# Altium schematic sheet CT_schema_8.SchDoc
size 308 x 210 mm
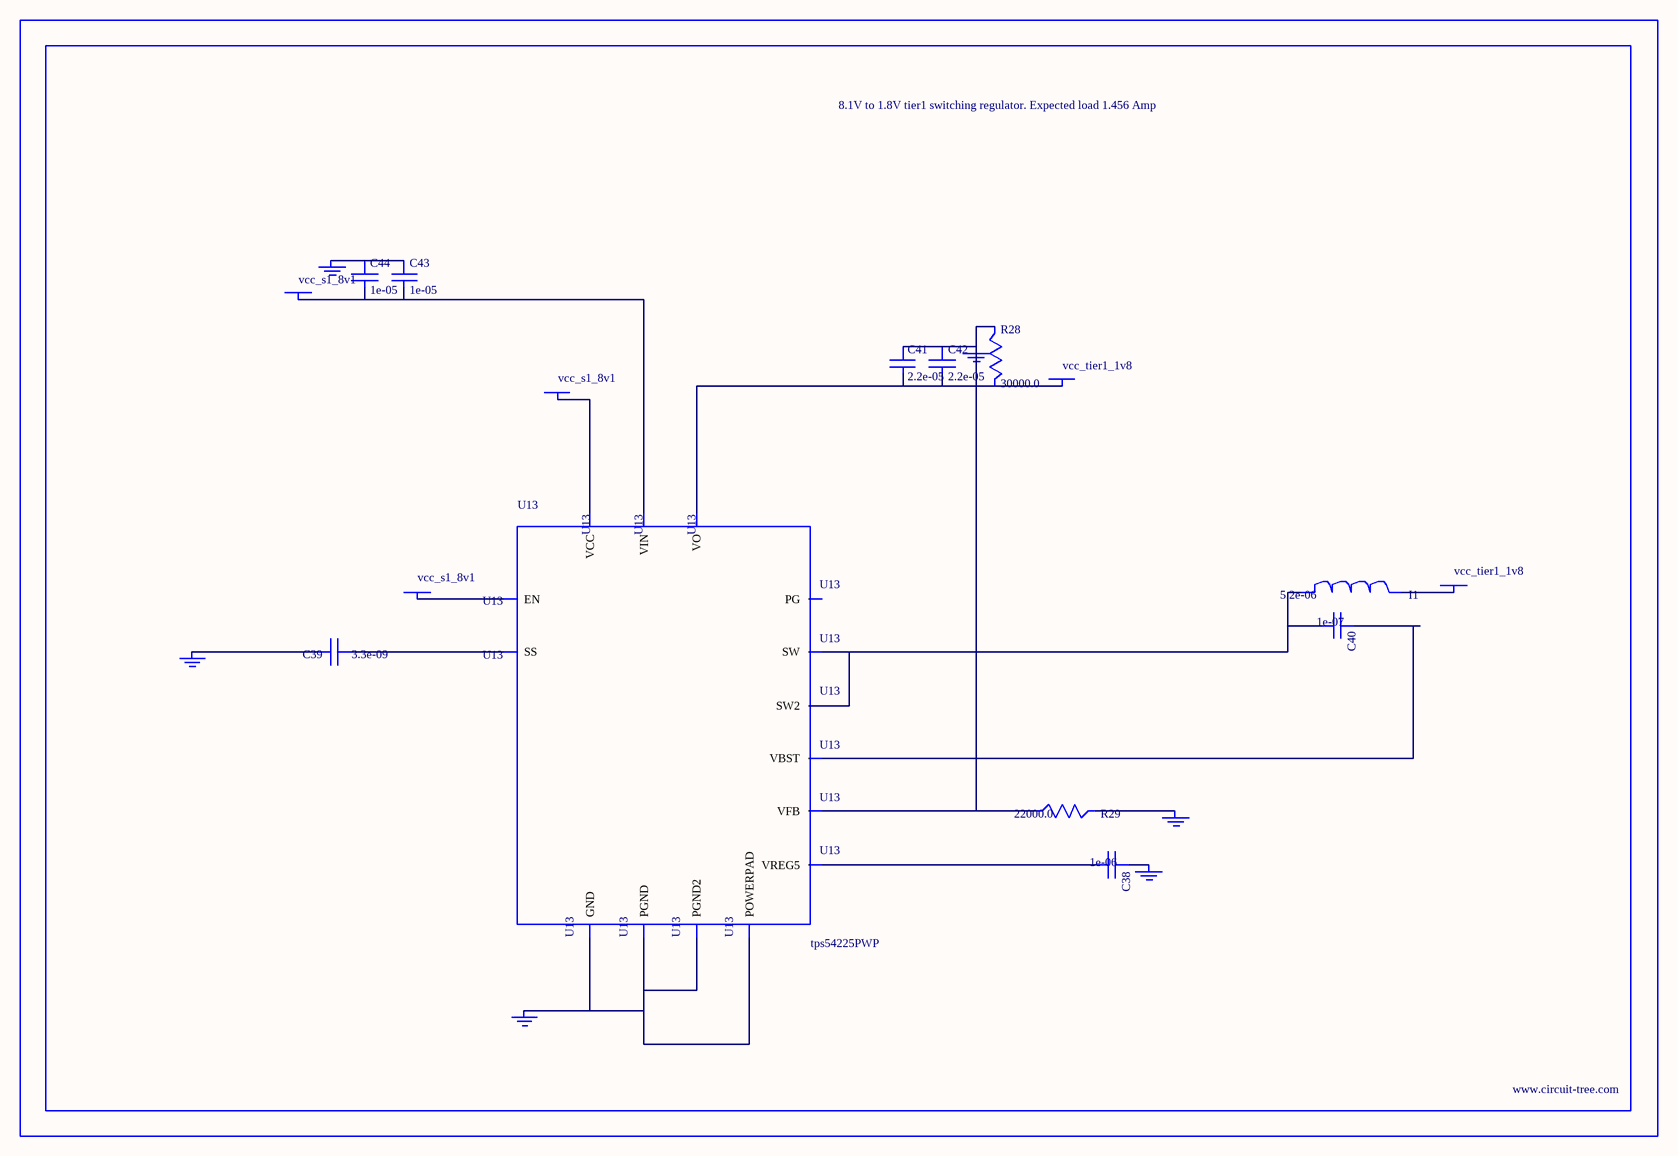
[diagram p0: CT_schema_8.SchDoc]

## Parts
BORDER7  (no value)
C38  1e-06  [C0603]
C39  3.3e-09  [C0402]
C40  1e-07  [C0402]
C41  2.2e-05  [C1210]
C42  2.2e-05  [C1210]
C43  1e-05  [C1206]
C44  1e-05  [C1206]
GND_INSTANCE_7_0  (no value)
GND_INSTANCE_7_1  (no value)
GND_INSTANCE_7_2  (no value)
GND_INSTANCE_7_3  (no value)
GND_INSTANCE_7_4  (no value)
GND_INSTANCE_7_5  (no value)
I1  5.2e-06  [DR1040]
POWER_INSTANCE_7_0  vcc_tier1_1v8
POWER_INSTANCE_7_1  vcc_s1_8v1
POWER_INSTANCE_7_2  vcc_tier1_1v8
POWER_INSTANCE_7_3  vcc_s1_8v1
POWER_INSTANCE_7_4  vcc_s1_8v1
R28  30000.0  [R0603]
R29  22000.0  [R0603]
U13  tps54225PWP  [HTSSOP14]

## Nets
NetC38_1: C38.1 GND_INSTANCE_7_2.0(GND)
NetC38_2: C38.2 U13.3(VREG5)
NetC39_1: C39.1 U13.4(SS)
NetC39_2: C39.2 GND_INSTANCE_7_3.0(GND)
NetC40_1: C40.1 U13.12(VBST)
NetC40_2: C40.2 I1.1 U13.10(SW) U13.11(SW2)
NetC41_1: C41.1 C42.1 GND_INSTANCE_7_0.0(GND) R28.1 R29.1 U13.2(VFB)
NetC41_2: C41.2 C42.2 POWER_INSTANCE_7_0.0(PWR) R28.2 U13.1(VO)
NetC43_1: C43.1 C44.1 GND_INSTANCE_7_5.0(GND)
NetC43_2: C43.2 C44.2 POWER_INSTANCE_7_3.0(PWR) U13.13(VIN)
NetGND_INSTANCE_7_1_0: GND_INSTANCE_7_1.0(GND) R29.2
NetGND_INSTANCE_7_4_0: GND_INSTANCE_7_4.0(GND) U13.5(GND) U13.8(PGND) U13.9(PGND2) U13.15(POWERPAD)
NetI1_2: I1.2 POWER_INSTANCE_7_2.0(PWR)
NetPOWER_INSTANCE_7_1_0: POWER_INSTANCE_7_1.0(PWR) U13.7(EN)
NetPOWER_INSTANCE_7_4_0: POWER_INSTANCE_7_4.0(PWR) U13.14(VCC)

Not connected (* = marked no-connect by the designer): U13 6(PG)

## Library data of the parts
BORDER7 = BORDER_PAGE7
C38 = C0603C105K3RACTU
C39 = C0402C332K3RAC
C40 = C0402C104K3RACTU
C41 C42 = GRM32ER61E226ME15L
C43 C44 = C1206C106K3RACTU
GND_INSTANCE_7_0-GND_INSTANCE_7_5 = GND
I1 = DR1040-5R2-R
POWER_INSTANCE_7_0-POWER_INSTANCE_7_4 = PWR
R28 = RC0603JR-0730KL
R29 = RC0603JR-0722KL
